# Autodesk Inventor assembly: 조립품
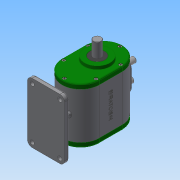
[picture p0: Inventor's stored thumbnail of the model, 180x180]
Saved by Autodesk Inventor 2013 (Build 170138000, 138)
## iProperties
Created: 2018-10
Part Number: 조립품
Document SubType Name: Assembly
Designer: Administrator
Author: Administrator
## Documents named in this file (15)
- C:\Users\Administrator\Desktop\381007V1012\답안조립품.iam
- C:\Users\Administrator\Desktop\381007V1012\본체.ipt
- C:\Users\Administrator\Desktop\381007V1012\뒤커버.ipt
- C:\Users\Administrator\Desktop\381007V1012\메인축.ipt
- C:\Users\Administrator\Desktop\381007V1012\베어링 608.ipt
- C:\Users\Administrator\Desktop\381007V1012\베어링 6003.ipt
- C:\Users\Administrator\Desktop\381007V1012\볼트 M4.ipt
- C:\Users\Administrator\Desktop\381007V1012\부시.ipt
- C:\Users\Administrator\Desktop\381007V1012\서브축.ipt
- C:\Users\Administrator\Desktop\381007V1012\슬라이더.ipt
- C:\Users\Administrator\Desktop\381007V1012\앞커버.ipt
- C:\Users\Administrator\Desktop\381007V1012\오일실 8 22 7.ipt
- C:\Users\Administrator\Desktop\381007V1012\오일실 17 32 8.ipt
- C:\Users\Administrator\Desktop\381007V1012\가변스프링.ipt
- C:\Users\Administrator\Desktop\381007V1012\가변스프링2.ipt
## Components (2 placed, 2 different names)
1. 가변스프링:1
2. 가변스프링2:1
